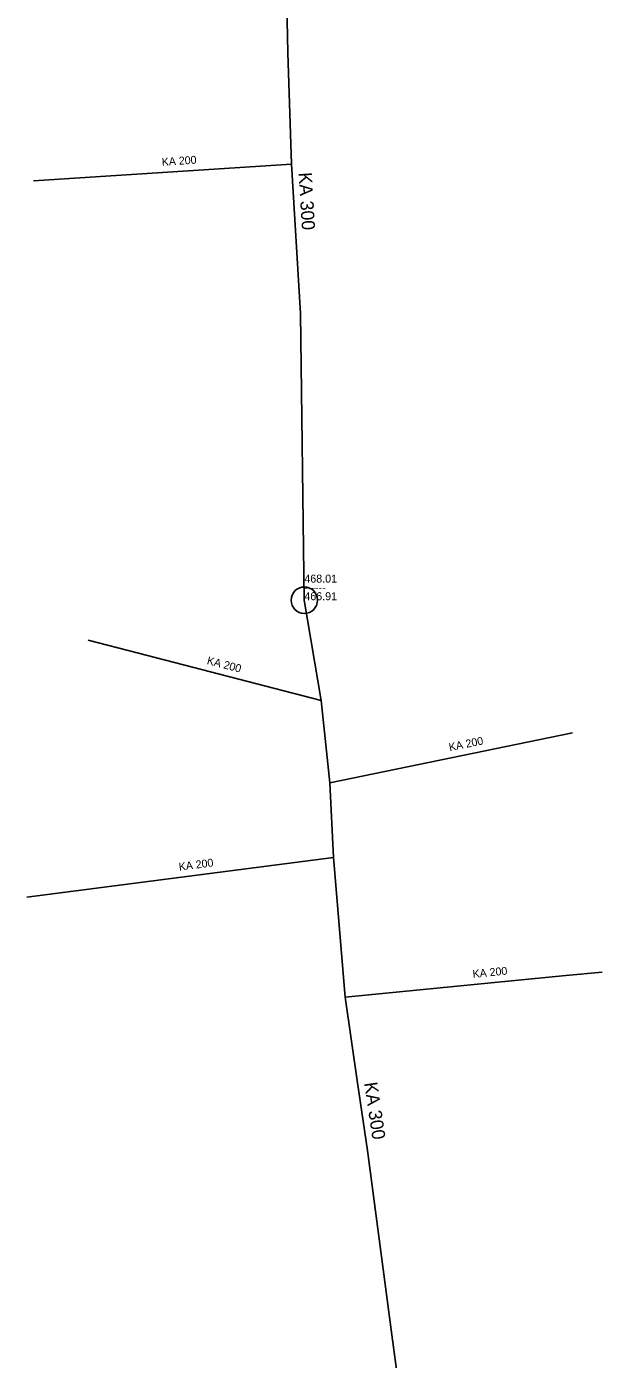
# Model space of a CAD drawing. Extents: x -684724 to -684322, y -1163905 to -1163488.
# Drawn here: x -684474.5 to -684452.7, y -1163614.8 to -1163564.3 of the extents above; entities that cross this region are included whole.
import ezdxf

# ---------------------------------------------------------------- set-up
doc = ezdxf.new("R2010")
doc.units = 0
for name, color, linetype in [('Kanalizační přípojky', 7, 'Continuous'), ('Kanalizační stoka', 7, 'Continuous'), ('Kanalizační šachty', 7, 'Continuous'), ('Popis', 7, 'Continuous')]:
    doc.layers.add(name, color=color, linetype=linetype)

msp = doc.modelspace()

# ---------------------------------------------------------------- linework, layer by layer
at = {"layer": 'Kanalizační přípojky'}
for points in [[(-684474.28, -1163570.16), (-684464.52, -1163569.52)], [(-684472.21, -1163587.55), (-684470.36, -1163588.03), (-684463.39, -1163589.84)], [(-684453.88, -1163591.06), (-684463.07, -1163592.95)], [(-684474.54, -1163597.29), (-684462.92, -1163595.78)], [(-684452.75, -1163600.12), (-684454.13, -1163600.25), (-684462.49, -1163601.07)]]:
    msp.add_lwpolyline(points, dxfattribs=at)
at = {"layer": 'Kanalizační stoka'}
for points in [[(-684464.52, -1163553.69), (-684464.62, -1163555.11), (-684464.82, -1163557.93), (-684464.77, -1163559.79), (-684464.65, -1163565.31), (-684464.52, -1163569.52), (-684464.18, -1163575.18), (-684464.03, -1163586.04)], [(-684464.03, -1163586.04), (-684463.39, -1163589.84), (-684463.07, -1163592.95), (-684462.92, -1163595.78), (-684462.49, -1163601.07), (-684462.02, -1163604.32), (-684461.64, -1163606.88), (-684460.72, -1163613.86), (-684459.64, -1163621.83), (-684459.48, -1163622.63)]]:
    msp.add_lwpolyline(points, dxfattribs=at)
at = {"layer": 'Kanalizační šachty'}
msp.add_circle((-684464.03, -1163586.04), 0.5, dxfattribs=at)

# ---------------------------------------------------------------- texts
at = {"layer": 'Popis'}
for s, height, rotation, p in [('KA 200', 0.3, 3.7517, (-684469.416, -1163569.591)), ('KA 300', 0.5, 273.4377, (-684464.25, -1163569.848)), ('468.01', 0.303, 0, (-684464.03, -1163585.373)), ('------', 0.303, 0, (-684464.03, -1163585.707)), ('466.91', 0.303, 0, (-684464.03, -1163586.04)), ('KA 200', 0.3, 345.4427, (-684467.737, -1163588.453)), ('KA 200', 0.3, 11.6213, (-684458.525, -1163591.76)), ('KA 200', 0.3, 7.404, (-684468.762, -1163596.287)), ('KA 200', 0.3, 5.602, (-684457.645, -1163600.344)), ('KA 300', 0.5, 278.4432, (-684461.767, -1163604.324))]:
    msp.add_text(s, height=height, rotation=rotation, dxfattribs=at).set_placement(p)

doc.saveas('drawing.dxf')
